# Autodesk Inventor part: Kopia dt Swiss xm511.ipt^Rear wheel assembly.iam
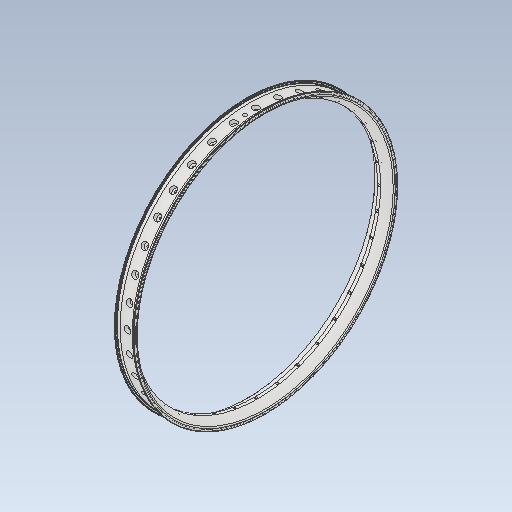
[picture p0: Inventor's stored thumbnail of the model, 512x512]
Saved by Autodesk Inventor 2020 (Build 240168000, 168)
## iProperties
Created: 2017-09
Part Number: Kopia dt Swiss xm511.ipt^Rear wheel assembly.iam
Material: Ogólny
Document SubType Name: Modeling
Designer: Tomasz
Density: 1 g/cm^3
Appearance: Domyślna
Sending System: SolidWorks 2017
Last Author: Tomasz
Last Saved: 2017-09-11
Author: Tomasz
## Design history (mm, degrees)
feature "dt Swiss xm511.ipt"
node "Bryła1"
